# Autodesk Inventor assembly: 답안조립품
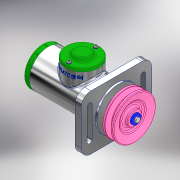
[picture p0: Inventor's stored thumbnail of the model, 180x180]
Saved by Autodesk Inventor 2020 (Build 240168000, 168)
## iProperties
Created: 2021-07
Part Number: 답안조립품
Document SubType Name: Assembly
Designer: MIRAE
Author: MIRAE
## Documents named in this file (20)
- C:\Users\MIRAE\Desktop\710706V1024\답안조립품.iam
- C:\Users\MIRAE\Desktop\710706V1024\본체.ipt
- C:\Users\MIRAE\Desktop\710706V1024\축.ipt
- C:\Users\MIRAE\Desktop\710706V1024\부시1.ipt
- C:\Users\MIRAE\Desktop\710706V1024\베어링 15 x 35 x 11.ipt
- C:\Users\MIRAE\Desktop\710706V1024\멈춤링 15 x 1.ipt
- C:\Users\MIRAE\Desktop\710706V1024\멈춤링 35 x 1.6.ipt
- C:\Users\MIRAE\Desktop\710706V1024\부시2.ipt
- C:\Users\MIRAE\Desktop\710706V1024\와셔 10 x 21.ipt
- C:\Users\MIRAE\Desktop\710706V1024\너트 M10.ipt
- C:\Users\MIRAE\Desktop\710706V1024\오일 실 15 25 7.ipt
- C:\Users\MIRAE\Desktop\710706V1024\사이드 커버.ipt
- 사이드 커버.ipt
- C:\Users\MIRAE\Desktop\710706V1024\키 4 x 4 x 18.ipt
- C:\Users\MIRAE\Desktop\710706V1024\V-벨트풀리.ipt
- C:\Users\MIRAE\Desktop\710706V1024\와셔 4 x 16.ipt
- C:\Users\MIRAE\Desktop\710706V1024\볼트 M4 x 10.ipt
- C:\Users\MIRAE\Desktop\710706V1024\탑 커버.ipt
- C:\Users\MIRAE\Desktop\710706V1024\와셔 3 x 6.ipt
- C:\Users\MIRAE\Desktop\710706V1024\십자볼트 M3 x 10.ipt
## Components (2 placed, 2 different names)
1. V-벨트풀리:1
2. ISO 4017 M4 x 10:1
